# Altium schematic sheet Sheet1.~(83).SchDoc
size A3
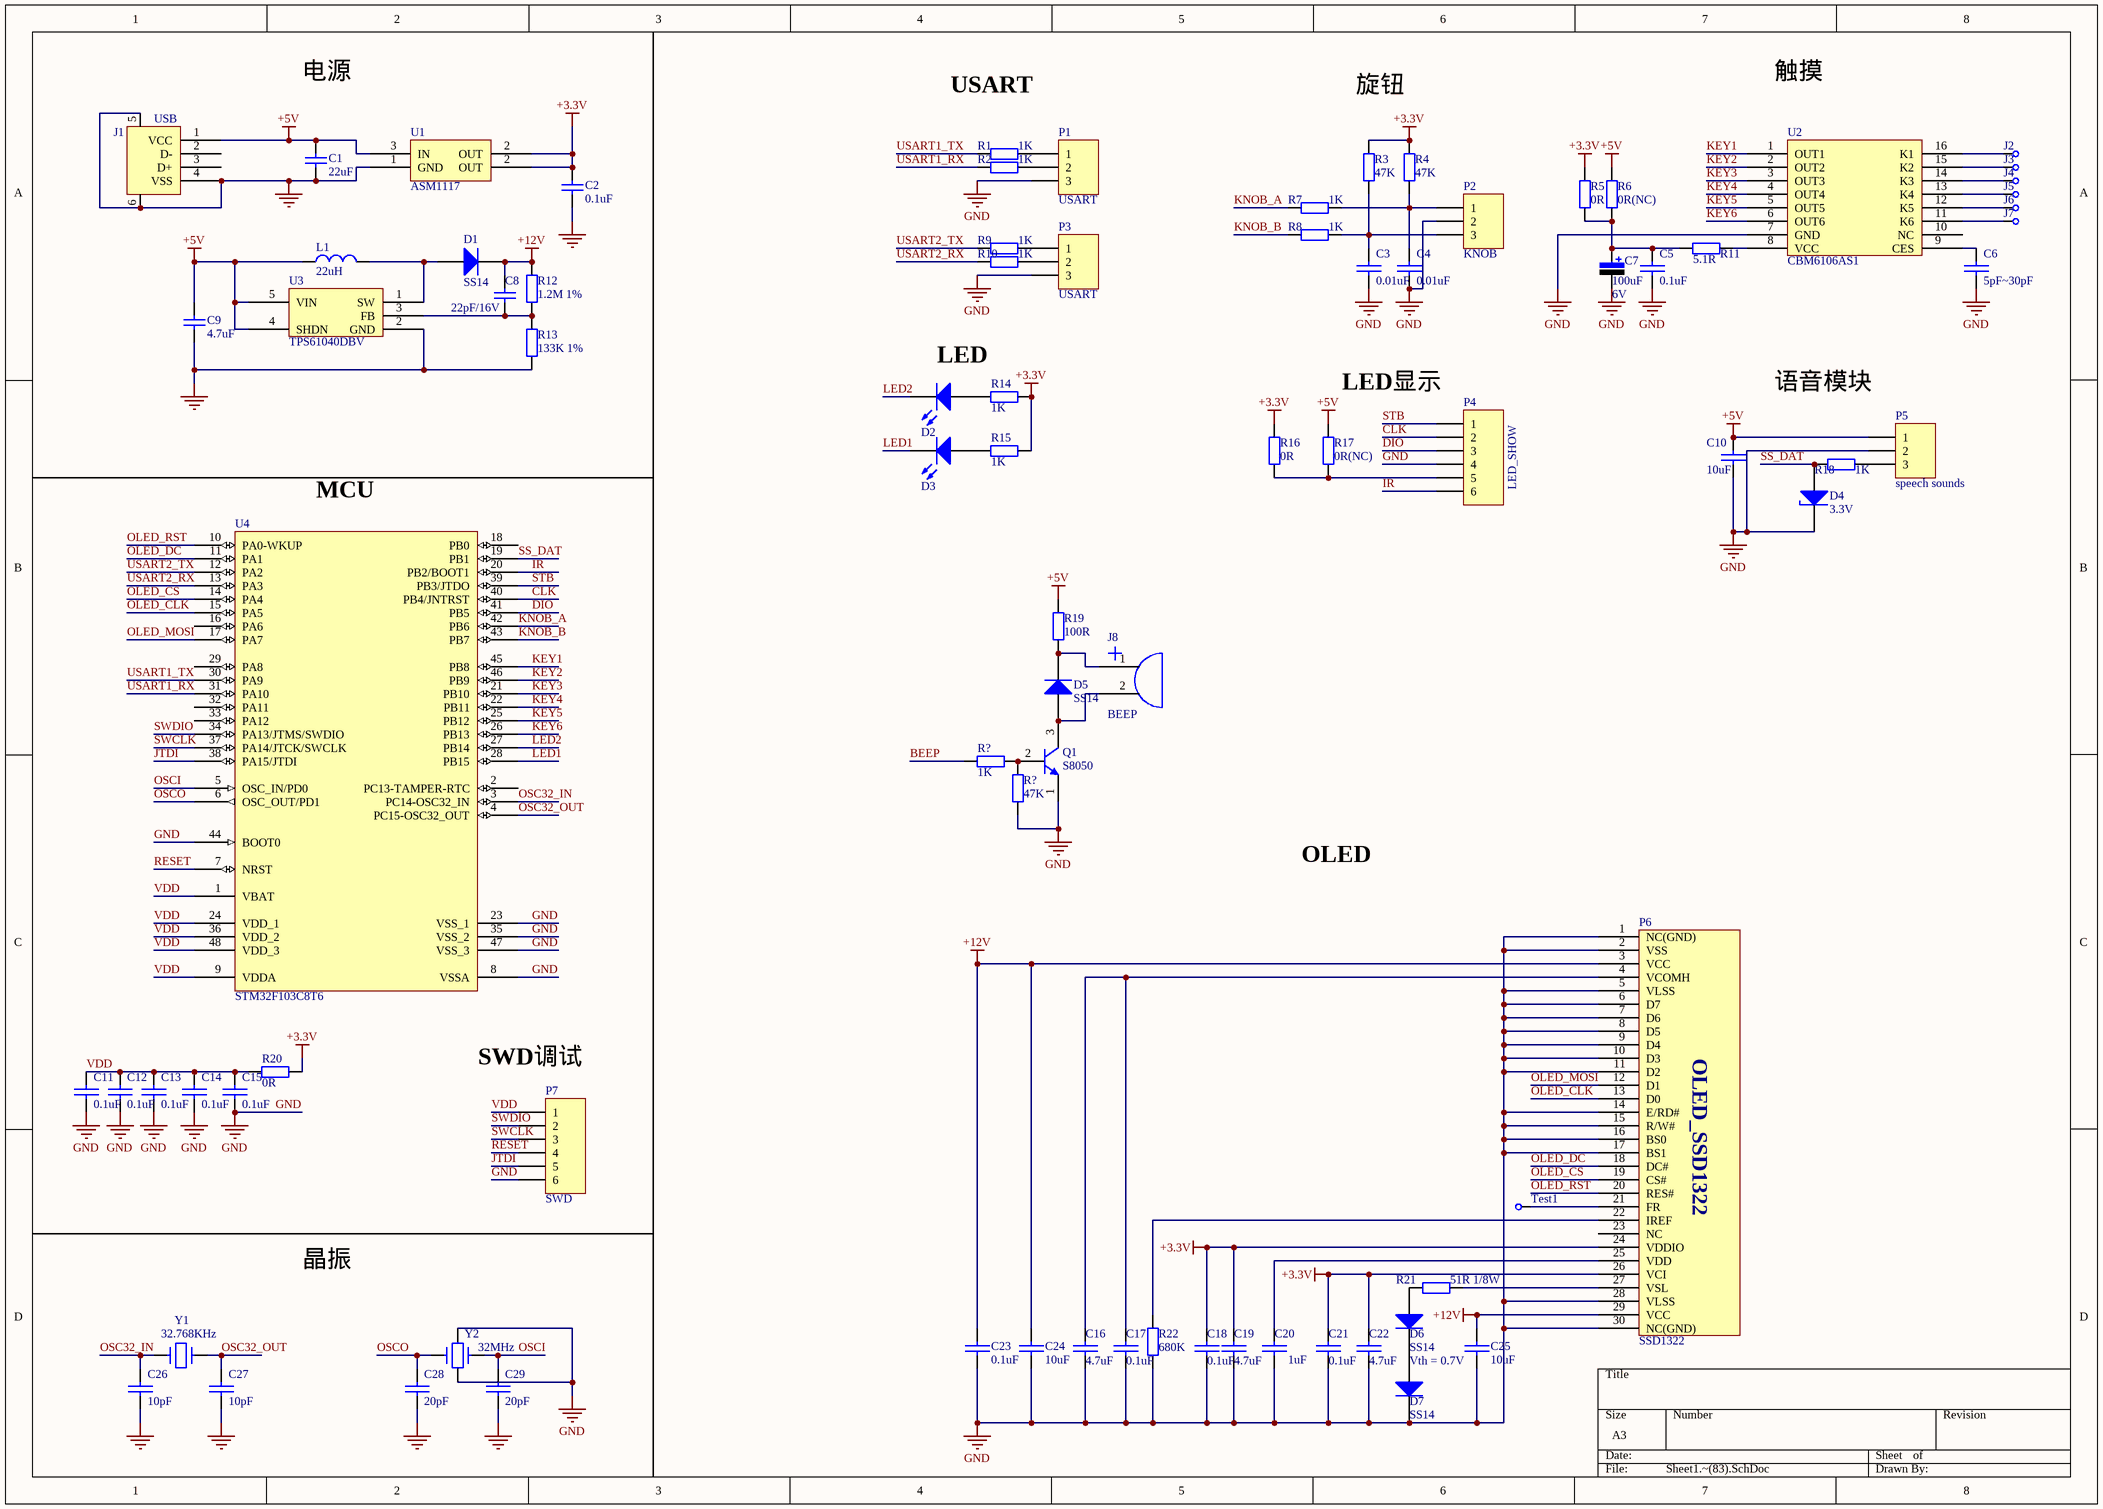
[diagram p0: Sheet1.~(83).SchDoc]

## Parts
(Parts that share a designator on the sheet are numbered #1, #2 ... from top to bottom, then left to right.)
C1  value 22uF  [0402C]  (hidden comment: Cap)
C2  value 0.1uF  [0402C]  (hidden comment: Cap)
C3  0.01uF  [0402C]
C4  0.01uF  [0402C]
C5  0.1uF  [0402C]
C6  5pF~30pF  [0402C]
C7  value 100uF  Vol: 6V  [CAP-3528]  (hidden comment: Cap Pol)
C8  value 22pF/16V  [0402C]  (hidden comment: Cap)
C9  value 4.7uF  [0402C]  (hidden comment: Cap)
C10  10uF  [0402C]
C11  0.1uF  [0402C]
C12  0.1uF  [0402C]
C13  0.1uF  [0402C]
C14  0.1uF  [0402C]
C15  0.1uF  [0402C]
C16  4.7uF  [0402C]
C17  0.1uF  [0402C]
C18  0.1uF  [0402C]
C19  4.7uF  [0402C]
C20  1uF  [0402C]
C21  0.1uF  [0402C]
C22  4.7uF  [0402C]
C23  0.1uF  [0402C]
C24  10uF  [0402C]
C25  10uF  [0402C]
C26  10pF  [0402C]
C27  10pF  [0402C]
C28  20pF  [0402C]
C29  20pF  [0402C]
D1  Type: SS14  [DIODE-1206]  (hidden comment: Diode)
D2  LED0  [led0603]  (value not drawn)
D3  LED0  [led0603]  (value not drawn)
D4  value 3.3V  [DIODE-1206]  (hidden comment: Diode-Z)
D5  Type: SS14  [DIODE-1206]  (hidden comment: Diode)
D6  Type: SS14  [DIODE-1206]  (hidden comment: Diode)
D7  Type: SS14  [DIODE-1206]  (hidden comment: Diode)
J1  USB  [USB_A1]
J2  CHECK  [CHECK-A]  (value not drawn)
J3  CHECK  [CHECK-A]  (value not drawn)
J4  CHECK  [CHECK-A]  (value not drawn)
J5  CHECK  [CHECK-A]  (value not drawn)
J6  CHECK  [CHECK-A]  (value not drawn)
J7  CHECK  [CHECK-A]  (value not drawn)
J8  BEEP  [Beep]
L1  value 22uH  [1206]  (hidden comment: Inductor)
P1  USART  [HDR3X1_A]
P2  KNOB  [HDR3X1_A]
P3  USART  [HDR3X1_A]
P4  LED_SHOW  [HDR6X1_B2]
P5  speech sounds  [HDR3X1_A]
P6  SSD1322
P7  SWD  [HDR6X1_B2]
Q1  S8050  [TO-92A]
R1  value 1K  [0402R]  (hidden comment: Res1)
R2  value 1K  [0402R]  (hidden comment: Res1)
R3  value 47K  [0603-1]  (hidden comment: Res1)
R4  value 47K  [0603-1]  (hidden comment: Res1)
R5  value 0R  [0402R]  (hidden comment: Res1)
R6  value 0R(NC)  [0402R]  (hidden comment: Res1)
R7  value 1K  [0603-1]  (hidden comment: Res1)
R8  value 1K  [0603-1]  (hidden comment: Res1)
R9  value 1K  [0402R]  (hidden comment: Res1)
R10  value 1K  [0402R]  (hidden comment: Res1)
R11  value 5.1R  [0603-1]  (hidden comment: Res1)
R12  value 1.2M 1%  [0402R]  (hidden comment: Res1)
R13  value 133K 1%  [0402R]  (hidden comment: Res1)
R14  value 1K  [0402R]  (hidden comment: Res1)
R15  value 1K  [0402R]  (hidden comment: Res1)
R16  value 0R  [0402R]  (hidden comment: Res1)
R17  value 0R(NC)  [0402R]  (hidden comment: Res1)
R18  value 1K  [0402R]  (hidden comment: Res1)
R19  value 100R  [0402R]  (hidden comment: Res1)
R20  value 0R  [0402R]  (hidden comment: Res1)
R21  value 51R 1/8W  [0402R]  (hidden comment: Res1)
R22  value 680K  [0402R]  (hidden comment: Res1)
R?#1  value 1K  [0402R]  (hidden comment: Res1)
R?#2  value 47K  [0402R]  (hidden comment: Res1)
Test1  CHECK  [CHECK-A]  (value not drawn)
U1  ASM1117  [SOT-223-3]
U2  CBM6106AS1
U3  TPS61040DBV
U4  STM32F103C8T6  [LQFP48_N]
Y1  32.768KHz  [SMD3215]
Y2  32MHz  [Y3225]

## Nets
+3.3V: C2.2 C18.1 C19.1 C21.1 C22.1 P6.24(VDDIO) P6.26(VCI) R3.2 R4.2 R5.1 R14.1 R15.1 R16.1 R20.2 U1.2(OUT)
+5V: C1.2 C9.2 C10.1 J1.1(VCC) L1.1 P5.1 R6.1 R17.1 R19.1 U1.3(IN) U3.4(SHDN) U3.5(VIN)
+12V: C8.2 C23.2 C24.2 C25.2 D1.2(K) P6.3(VCC) P6.29(VCC) R12.1
GND: C1.1 C2.1 C3.2 C4.2 C5.2 C6.2 C7.2 C9.1 C10.2 C11.2 C12.2 C13.2 C14.2 C15.2 C16.2 C17.2 C18.2 C19.2 C20.2 C21.2 C22.2 C23.1 C24.1 C25.1 C26.2 C27.2 C28.2 C29.2 D4.2(K) D7.2(K) J1.4(VSS) J1.5 J1.6 P1.3 P2.2 P3.3 P4.4 P5.2 P6.1(NC(GND)) P6.2(VSS) P6.5(VLSS) P6.6(D7) P6.7(D6) P6.8(D5) P6.9(D4) P6.10(D3) P6.11(D2) P6.14(E/RD#) P6.15(R/W#) P6.16(BS0) P6.17(BS1) P6.28(VLSS) P6.30(NC(GND)) P7.6 Q1.1(E) R13.2 R22.2 R?#2.1 U1.1(GND) U2.7(GND) U3.2(GND) U4.8(VSSA) U4.23(VSS_1) U4.35(VSS_2) U4.44(BOOT0) U4.47(VSS_3) Y2.2 Y2.4
BEEP: R?#1.1
CLK: P4.2 U4.40(PB4/JNTRST)
DIO: P4.3 U4.41(PB5)
IR: P4.6 U4.20(PB2/BOOT1)
JTDI: P7.5 U4.38(PA15/JTDI)
KEY1: U2.1(OUT1) U4.45(PB8)
KEY2: U2.2(OUT2) U4.46(PB9)
KEY3: U2.3(OUT3) U4.21(PB10)
KEY4: U2.4(OUT4) U4.22(PB11)
KEY5: U2.5(OUT5) U4.25(PB12)
KEY6: U2.6(OUT6) U4.26(PB13)
KNOB_A: R7.1 U4.42(PB6)
KNOB_B: R8.1 U4.43(PB7)
LED1: D3.2(K) U4.28(PB15)
LED2: D2.2(K) U4.27(PB14)
OLED_CLK: P6.13(D0) U4.15(PA5)
OLED_CS: P6.19(CS#) U4.14(PA4)
OLED_DC: P6.18(DC#) U4.11(PA1)
OLED_MOSI: P6.12(D1) U4.17(PA7)
OLED_RST: P6.20(RES#) U4.10(PA0-WKUP)
OSC32_IN: C26.1 U4.3(PC14-OSC32_IN) Y1.1
OSC32_OUT: C27.1 U4.4(PC15-OSC32_OUT) Y1.2
OSCI: C29.1 U4.5(OSC_IN/PD0) Y2.3
OSCO: C28.1 U4.6(OSC_OUT/PD1) Y2.1
RESET: P7.4 U4.7(NRST)
SS_DAT: D4.1(A) R18.2 U4.19(PB1)
STB: P4.1 U4.39(PB3/JTDO)
SWCLK: P7.3 U4.37(PA14/JTCK/SWCLK)
SWDIO: P7.2 U4.34(PA13/JTMS/SWDIO)
USART1_RX: R2.2 U4.31(PA10)
USART1_TX: R1.2 U4.30(PA9)
USART2_RX: R10.2 U4.13(PA3)
USART2_TX: R9.2 U4.12(PA2)
VDD: C11.1 C12.1 C13.1 C14.1 C15.1 P7.1 R20.1 U4.1(VBAT) U4.9(VDDA) U4.24(VDD_1) U4.36(VDD_2) U4.48(VDD_3)
NetC3_1: C3.1 P2.3 R3.1 R8.2
NetC4_1: C4.1 P2.1 R4.1 R7.2
NetC5_1: C5.1 C7.1 R5.2 R6.2 R11.1
NetC6_1: C6.1 U2.9(CES)
NetC8_1: C8.1 R12.2 R13.1 U3.3(FB)
NetC16_1: C16.1 C17.1 P6.4(VCOMH)
NetC20_1: C20.1 P6.25(VDD)
NetD1_1: D1.1(A) L1.2 U3.1(SW)
NetD2_1: D2.1(A) R14.2
NetD3_1: D3.1(A) R15.2
NetD5_1: D5.1(A) J8.2 Q1.3(C)
NetD5_2: D5.2(K) J8.1 R19.2
NetD6_1: D6.1(A) R21.2
NetD6_2: D6.2(K) D7.1(A)
NetJ2_1: J2.1 U2.16(K1)
NetJ3_1: J3.1 U2.15(K2)
NetJ4_1: J4.1 U2.14(K3)
NetJ5_1: J5.1 U2.13(K4)
NetJ6_1: J6.1 U2.12(K5)
NetJ7_1: J7.1 U2.11(K6)
NetP1_1: P1.1 R1.1
NetP1_2: P1.2 R2.1
NetP3_1: P3.1 R9.1
NetP3_2: P3.2 R10.1
NetP4_5: P4.5 R16.2 R17.2
NetP5_3: P5.3 R18.1
NetP6_21: P6.21(FR) Test1.1
NetP6_22: P6.22(IREF) R22.1
NetP6_27: P6.27(VSL) R21.1
NetQ1_2: Q1.2(B) R?#1.2 R?#2.2
NetR11_2: R11.2 U2.8(VCC)

Not connected (* = marked no-connect by the designer): J1 2(D-) 3(D+); P6 23(NC); U2 10(NC); U4 2(PC13-TAMPER-RTC) 16(PA6) 18(PB0) 29(PA8) 32(PA11) 33(PA12)

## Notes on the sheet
- 电源
- USART
- 旋钮
- 触摸
- LED
- LED显示
- 语音模块
- (near U4) MCU
- OLED
- (near P7) SWD调试
- 晶振
- Vth = 0.7V

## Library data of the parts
C1 C2 C8 C9 = Cap: 无极性电容
C3-C6 C10-C29 = CAP: Capacitor
C7 = Cap Pol: 极性电解电容
D1 D5-D7 = Diode: 二极管
D2 D3 = LED0: 发光二极管
D4 = Diode-Z: 稳压二极管
J1 = USB: USB接口
J2-J7 Test1 = CHECK: 测试点
J8 = BEEP: 蜂鸣器
L1 = Inductor: 电感; Code_IEC: 1005
P1-P3 P5 = Header 3: 接插件
P4 P7 = Header 6: 接插件
Q1 = S8050: NPN三极管
R1-R22 R?#1 R?#2 = Res1: 贴片电阻
U1 = ASM1117: 3.3V稳压芯片
U4 = STM32F103C8T6: STM32 ARM-based 32-bit MCU with 64 Kbytes Flash, 48-pin LQFP, Industrial Temperature
Y1 = CRYSTAL
Y2 = CRYSTAL1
